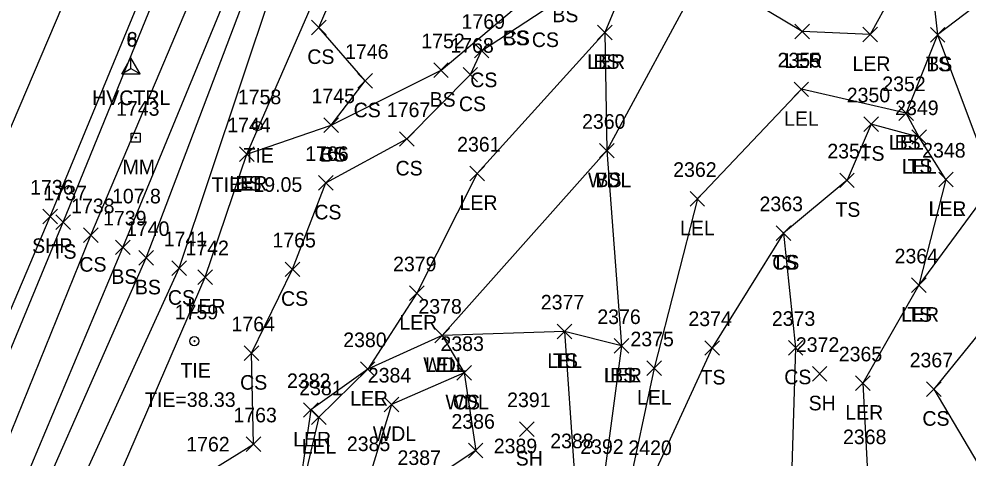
# Model space of a CAD drawing. Extents: x 1483143 to 1488182, y 802902 to 807581.
# Drawn here: x 1487782.5 to 1487912.6, y 806252.6 to 806312.7 of the extents above; entities that cross this region are included whole.
import ezdxf

# ---------------------------------------------------------------- set-up
doc = ezdxf.new("R2010")
doc.units = 0
for name, color, linetype in [('C_A', 7, 'Continuous'), ('C_C', 7, 'Continuous'), ('C_I', 7, 'Continuous'), ('CBP', 7, 'Continuous'), ('CPSM', 7, 'Continuous'), ('L_A', 7, 'Continuous'), ('L_I', 7, 'Continuous'), ('L_TIC', 7, 'Continuous'), ('LARO', 7, 'Continuous'), ('LAWA', 7, 'Continuous'), ('LELB', 7, 'Continuous'), ('P_A', 7, 'Continuous'), ('P_I', 7, 'Continuous'), ('P_TIC', 7, 'Continuous'), ('PET', 7, 'Continuous'), ('PSP', 7, 'Continuous'), ('S_A', 7, 'Continuous'), ('S_C', 7, 'Continuous'), ('S_I', 7, 'Continuous'), ('SRM', 7, 'Continuous')]:
    doc.layers.add(name, color=color, linetype=linetype)

msp = doc.modelspace()

# ---------------------------------------------------------------- linework, layer by layer
at = {"layer": 'CBP'}
for centre, radius in [((1487815.21, 806298.01), 0.625), ((1487815.21, 806298.01), 0.0833), ((1487806.57, 806268.56), 0.625), ((1487806.57, 806268.56), 0.0833)]:
    msp.add_circle(centre, radius, dxfattribs=at)
at = {"layer": 'CPSM'}
for p, q in [((1487796.61, 806305.17), (1487797.86, 806307.34)), ((1487796.62, 806305.17), (1487797.87, 806307.34)), ((1487799.11, 806305.17), (1487797.86, 806307.34)), ((1487797.86, 806305.89), (1487797.86, 806307.34)), ((1487799.12, 806305.17), (1487797.87, 806307.34)), ((1487797.87, 806305.9), (1487797.87, 806307.34)), ((1487796.61, 806305.17), (1487797.86, 806305.89)), ((1487796.61, 806305.17), (1487799.11, 806305.17)), ((1487796.62, 806305.17), (1487797.87, 806305.9)), ((1487796.62, 806305.17), (1487799.12, 806305.17)), ((1487797.86, 806305.89), (1487797.86, 806305.89)), ((1487797.86, 806305.89), (1487799.11, 806305.17)), ((1487797.87, 806305.9), (1487797.87, 806305.9)), ((1487797.87, 806305.9), (1487799.12, 806305.17))]:
    msp.add_line(p, q, dxfattribs=at)
at = {"layer": 'L_TIC'}
for points in [[(1487822.6, 806310.52), (1487824.6, 806312.52)], [(1487824.6, 806310.52), (1487822.6, 806312.52)], [(1487861.81, 806309.84), (1487863.81, 806311.84)], [(1487863.81, 806309.84), (1487861.81, 806311.84)], [(1487861.81, 806309.84), (1487863.81, 806311.84)], [(1487863.81, 806309.84), (1487861.81, 806311.84)], [(1487888.85, 806309.98), (1487890.85, 806311.98)], [(1487890.85, 806309.98), (1487888.85, 806311.98)], [(1487898.17, 806309.55), (1487900.17, 806311.55)], [(1487900.17, 806309.55), (1487898.17, 806311.55)], [(1487907.42, 806309.52), (1487909.42, 806311.52)], [(1487909.42, 806309.52), (1487907.42, 806311.52)], [(1487907.42, 806309.52), (1487909.42, 806311.52)], [(1487909.42, 806309.52), (1487907.42, 806311.52)], [(1487844.93, 806307.34), (1487846.93, 806309.34)], [(1487846.93, 806307.34), (1487844.93, 806309.34)], [(1487839.36, 806304.67), (1487841.36, 806306.67)], [(1487841.36, 806304.67), (1487839.36, 806306.67)], [(1487828.95, 806303.22), (1487830.95, 806305.22)], [(1487830.95, 806303.22), (1487828.95, 806305.22)], [(1487843.38, 806304.06), (1487845.38, 806306.06)], [(1487845.38, 806304.06), (1487843.38, 806306.06)], [(1487888.74, 806302.05), (1487890.74, 806304.05)], [(1487890.74, 806302.05), (1487888.74, 806304.05)], [(1487903.09, 806298.8), (1487905.09, 806300.8)], [(1487905.09, 806298.8), (1487903.09, 806300.8)], [(1487903.09, 806298.8), (1487905.09, 806300.8)], [(1487905.09, 806298.8), (1487903.09, 806300.8)], [(1487824.31, 806297.15), (1487826.31, 806299.15)], [(1487826.31, 806297.15), (1487824.31, 806299.15)], [(1487824.31, 806297.15), (1487826.31, 806299.15)], [(1487826.31, 806297.15), (1487824.31, 806299.15)], [(1487898.31, 806297.27), (1487900.31, 806299.27)], [(1487900.31, 806297.27), (1487898.31, 806299.27)], [(1487834.69, 806295.25), (1487836.69, 806297.25)], [(1487836.69, 806295.25), (1487834.69, 806297.25)], [(1487904.87, 806295.52), (1487906.87, 806297.52)], [(1487906.87, 806295.52), (1487904.87, 806297.52)], [(1487904.87, 806295.52), (1487906.87, 806297.52)], [(1487906.87, 806295.52), (1487904.87, 806297.52)], [(1487812.76, 806293.17), (1487814.76, 806295.17)], [(1487814.76, 806293.17), (1487812.76, 806295.17)], [(1487812.76, 806293.17), (1487814.76, 806295.17)], [(1487814.76, 806293.17), (1487812.76, 806295.17)], [(1487862.09, 806293.65), (1487864.09, 806295.65)], [(1487864.09, 806293.65), (1487862.09, 806295.65)], [(1487862.09, 806293.65), (1487864.09, 806295.65)], [(1487864.09, 806293.65), (1487862.09, 806295.65)], [(1487844.31, 806290.53), (1487846.31, 806292.53)], [(1487846.31, 806290.53), (1487844.31, 806292.53)], [(1487823.56, 806289.24), (1487825.56, 806291.24)], [(1487825.56, 806289.24), (1487823.56, 806291.24)], [(1487895, 806289.59), (1487897, 806291.59)], [(1487897, 806289.59), (1487895, 806291.59)], [(1487908.56, 806289.7), (1487910.56, 806291.7)], [(1487910.56, 806289.7), (1487908.56, 806291.7)], [(1487908.56, 806289.7), (1487910.56, 806291.7)], [(1487910.56, 806289.7), (1487908.56, 806291.7)], [(1487874.49, 806287.06), (1487876.49, 806289.06)], [(1487876.49, 806287.06), (1487874.49, 806289.06)], [(1487787.58, 806283.85), (1487789.58, 806285.85)], [(1487789.58, 806283.85), (1487787.58, 806285.85)], [(1487886.31, 806282.36), (1487888.31, 806284.36)], [(1487888.31, 806282.36), (1487886.31, 806284.36)], [(1487886.31, 806282.36), (1487888.31, 806284.36)], [(1487888.31, 806282.36), (1487886.31, 806284.36)], [(1487791.36, 806282.08), (1487793.36, 806284.08)], [(1487793.36, 806282.08), (1487791.36, 806284.08)], [(1487795.75, 806280.41), (1487797.75, 806282.41)], [(1487797.75, 806280.41), (1487795.75, 806282.41)], [(1487798.97, 806278.97), (1487800.97, 806280.97)], [(1487800.97, 806278.97), (1487798.97, 806280.97)], [(1487803.48, 806277.55), (1487805.48, 806279.55)], [(1487805.48, 806277.55), (1487803.48, 806279.55)], [(1487819, 806277.4), (1487821, 806279.4)], [(1487821, 806277.4), (1487819, 806279.4)], [(1487807.03, 806276.33), (1487809.03, 806278.33)], [(1487809.03, 806276.33), (1487807.03, 806278.33)], [(1487904.83, 806275.22), (1487906.83, 806277.22)], [(1487906.83, 806275.22), (1487904.83, 806277.22)], [(1487904.83, 806275.22), (1487906.83, 806277.22)], [(1487906.83, 806275.22), (1487904.83, 806277.22)], [(1487836.06, 806274.13), (1487838.06, 806276.13)], [(1487838.06, 806274.13), (1487836.06, 806276.13)], [(1487839.52, 806268.33), (1487841.52, 806270.33)], [(1487841.52, 806268.33), (1487839.52, 806270.33)], [(1487839.52, 806268.33), (1487841.52, 806270.33)], [(1487841.52, 806268.33), (1487839.52, 806270.33)], [(1487856.3, 806268.9), (1487858.3, 806270.9)], [(1487858.3, 806268.9), (1487856.3, 806270.9)], [(1487856.3, 806268.9), (1487858.3, 806270.9)], [(1487858.3, 806268.9), (1487856.3, 806270.9)], [(1487864.1, 806266.91), (1487866.1, 806268.91)], [(1487866.1, 806266.91), (1487864.1, 806268.91)], [(1487864.1, 806266.91), (1487866.1, 806268.91)], [(1487866.1, 806266.91), (1487864.1, 806268.91)], [(1487864.1, 806266.91), (1487866.1, 806268.91)], [(1487866.1, 806266.91), (1487864.1, 806268.91)], [(1487876.52, 806266.63), (1487878.52, 806268.63)], [(1487878.52, 806266.63), (1487876.52, 806268.63)], [(1487887.96, 806266.66), (1487889.96, 806268.66)], [(1487889.96, 806266.66), (1487887.96, 806268.66)], [(1487813.39, 806265.92), (1487815.39, 806267.92)], [(1487815.39, 806265.92), (1487813.39, 806267.92)], [(1487829.31, 806263.75), (1487831.31, 806265.75)], [(1487831.31, 806263.75), (1487829.31, 806265.75)], [(1487829.31, 806263.75), (1487831.31, 806265.75)], [(1487831.31, 806263.75), (1487829.31, 806265.75)], [(1487842.55, 806263.22), (1487844.55, 806265.22)], [(1487844.55, 806263.22), (1487842.55, 806265.22)], [(1487842.55, 806263.22), (1487844.55, 806265.22)], [(1487844.55, 806263.22), (1487842.55, 806265.22)], [(1487868.58, 806263.86), (1487870.58, 806265.86)], [(1487870.58, 806263.86), (1487868.58, 806265.86)], [(1487891.25, 806263.09), (1487893.25, 806265.09)], [(1487893.25, 806263.09), (1487891.25, 806265.09)], [(1487897.18, 806261.8), (1487899.18, 806263.8)], [(1487899.18, 806261.8), (1487897.18, 806263.8)], [(1487906.89, 806260.98), (1487908.89, 806262.98)], [(1487908.89, 806260.98), (1487906.89, 806262.98)], [(1487832.59, 806258.9), (1487834.59, 806260.9)], [(1487834.59, 806258.9), (1487832.59, 806260.9)], [(1487821.51, 806258.14), (1487823.51, 806260.14)], [(1487823.51, 806258.14), (1487821.51, 806260.14)], [(1487822.62, 806257.16), (1487824.62, 806259.16)], [(1487824.62, 806257.16), (1487822.62, 806259.16)], [(1487851.11, 806255.53), (1487853.11, 806257.53)], [(1487853.11, 806255.53), (1487851.11, 806257.53)], [(1487813.65, 806253.45), (1487815.65, 806255.45)], [(1487815.65, 806253.45), (1487813.65, 806255.45)], [(1487844.11, 806252.58), (1487846.11, 806254.58)], [(1487846.11, 806252.58), (1487844.11, 806254.58)]]:
    msp.add_lwpolyline(points, dxfattribs=at)
at = {"layer": 'LARO'}
for points in [[(1487666.95, 805964.97), (1487680.31, 805984.75), (1487702.99, 806037.2), (1487715.7, 806058.03), (1487734.3, 806108.53), (1487742.02, 806134.63), (1487761.66, 806177.53), (1487786.65, 806227.9), (1487808.03, 806277.33), (1487813.76, 806294.17), (1487828.9, 806329), (1487831.91, 806346.68), (1487843.29, 806372.21), (1487845.69, 806380.48), (1487852.63, 806386.9), (1487863.18, 806416.3)], [(1487938.33, 806405.75), (1487927.08, 806402.62), (1487919.67, 806403.09), (1487914.11, 806409.79), (1487906.78, 806399.47), (1487893.33, 806381.44), (1487887.6, 806370.68), (1487880.83, 806355.03), (1487873.24, 806335.95), (1487862.81, 806310.84), (1487845.31, 806291.53), (1487837.06, 806275.13), (1487830.31, 806264.75), (1487822.51, 806259.14), (1487820.37, 806244.37)], [(1487906.74, 806373.16), (1487907.59, 806351.7), (1487906.84, 806324.5), (1487899.17, 806310.55), (1487889.85, 806310.98), (1487876.29, 806319.09)], [(1487909.56, 806290.7), (1487905.87, 806296.52), (1487904.09, 806299.8), (1487889.74, 806303.05), (1487875.49, 806288.06), (1487869.58, 806264.86), (1487865.87, 806247.52), (1487863.99, 806239.72), (1487861.46, 806231.13), (1487859.56, 806216.52), (1487857.78, 806202.84), (1487854.62, 806182.96), (1487851.71, 806170.77)], [(1487909.56, 806290.7), (1487905.83, 806276.22), (1487898.18, 806262.8), (1487898.76, 806251.46), (1487896.26, 806247.35), (1487888.51, 806232.47), (1487866.93, 806215.67), (1487865.79, 806201.15), (1487860.88, 806184.43), (1487851.71, 806170.77)], [(1487865.1, 806267.91), (1487857.3, 806269.9), (1487840.52, 806269.33), (1487830.31, 806264.75), (1487823.62, 806258.16), (1487820.37, 806244.37)], [(1487865.1, 806267.91), (1487862.7, 806250.12), (1487854.75, 806240.93), (1487852, 806231.22), (1487849.04, 806223.36), (1487844.9, 806204.43)]]:
    msp.add_lwpolyline(points, dxfattribs=at)
at = {"layer": 'LAWA'}
msp.add_lwpolyline([(1487942.37, 806424.18), (1487942.13, 806400.96), (1487924.66, 806393.36), (1487906.74, 806373.16), (1487899.59, 806370.18), (1487890.83, 806350.54), (1487893.79, 806329.46), (1487876.29, 806319.09), (1487863.09, 806294.65), (1487840.52, 806269.33), (1487843.55, 806264.22), (1487833.59, 806259.9), (1487830.72, 806250.51), (1487828.92, 806235.37), (1487823.44, 806218.85), (1487816.5, 806198.3), (1487812.31, 806191.59), (1487811.73, 806182.07)], dxfattribs=at)
at = {"layer": 'LELB'}
for points in [[(1487959.91, 806445.22), (1487960.75, 806398.74), (1487951.5, 806373.39), (1487932.63, 806356.69), (1487906.84, 806324.5), (1487908.42, 806310.52), (1487916.06, 806290.13), (1487905.83, 806276.22)], [(1487406.66, 805485.41), (1487431.45, 805531.24), (1487454.84, 805575.74), (1487473.75, 805612.05), (1487489.43, 805642.37), (1487507.64, 805678.53), (1487524.82, 805711.39), (1487541.86, 805746.09), (1487557.67, 805776.44), (1487575.49, 805812.01), (1487597.52, 805857.93), (1487620.62, 805906.82), (1487641.85, 805951.94), (1487662.18, 805996.35), (1487684.09, 806043.93), (1487694.42, 806066.95), (1487726.58, 806140.7), (1487745.85, 806185.55), (1487769.04, 806237.65), (1487788.58, 806284.85), (1487808.3, 806333.26), (1487827.52, 806379.6), (1487850.09, 806437.73)], [(1487410.04, 805483.24), (1487436.07, 805529.53), (1487459.78, 805575.03), (1487477.42, 805609.67), (1487492.45, 805639.09), (1487509.86, 805677.27), (1487528.68, 805708.85), (1487545.3, 805744.17), (1487561.79, 805774.32), (1487579.7, 805810.21), (1487602.04, 805856.31), (1487624.97, 805905.57), (1487645.72, 805950.02), (1487667.21, 805993.1), (1487687.16, 806043.23), (1487699.2, 806065.16), (1487730.65, 806138.87), (1487749.96, 806183.58), (1487772.93, 806235.17), (1487792.36, 806283.08), (1487812.9, 806331.5), (1487831.61, 806378.23), (1487855.61, 806436.65)], [(1487413.83, 805481.53), (1487440.22, 805526.89), (1487464.36, 805572.85), (1487481.71, 805606.55), (1487496.63, 805636.25), (1487514.9, 805673.97), (1487535.8, 805705.94), (1487549.07, 805741.59), (1487566.17, 805772.22), (1487583.99, 805807.69), (1487605.26, 805855.28), (1487629.33, 805903.01), (1487650.26, 805948.76), (1487670.48, 805991.25), (1487690.28, 806041.74), (1487702.22, 806061.37), (1487704.47, 806066.39), (1487735.28, 806136.71), (1487754, 806182.42), (1487776.55, 806233.47), (1487796.75, 806281.41), (1487816.88, 806330.25), (1487835.19, 806376.59), (1487859.78, 806434.97)], [(1487417, 805480.8), (1487442.28, 805525.8), (1487466.47, 805571.82), (1487483.84, 805604.86), (1487498.25, 805635.76), (1487518.24, 805671.86), (1487538.47, 805704.77), (1487552.2, 805739.67), (1487568.17, 805771.84), (1487585.97, 805806.76), (1487609.39, 805853.47), (1487632.34, 805900.81), (1487653.02, 805947.32), (1487672.59, 805990.01), (1487694.92, 806039.27), (1487707.45, 806059.25), (1487710.05, 806064.3), (1487737.97, 806135.43), (1487757.4, 806181.42), (1487778.76, 806231.94), (1487799.97, 806279.97), (1487818.92, 806329.91), (1487837.5, 806376), (1487863.45, 806433.38)], [(1487539.8, 805706.7), (1487554.99, 805738.51), (1487564.78, 805761.24), (1487572.42, 805770.06), (1487590.42, 805804.18), (1487613.31, 805851.36), (1487639.64, 805896.3), (1487657.07, 805945.9), (1487666.95, 805964.97), (1487675.89, 805987.99), (1487698.82, 806037.9), (1487713.56, 806059.8), (1487740.03, 806134.78), (1487759.8, 806179.98), (1487782.43, 806230.23), (1487804.48, 806278.55), (1487821.45, 806329.34), (1487839.66, 806374.66), (1487865.87, 806433.14)], [(1487966.07, 806415.18), (1487969.53, 806392.86), (1487952.94, 806357.28), (1487940.19, 806330.57), (1487921.69, 806320.66), (1487908.42, 806310.52), (1487904.09, 806299.8)], [(1487808.19, 806250.46), (1487814.65, 806254.45), (1487814.39, 806266.92), (1487820, 806278.4), (1487824.56, 806290.24), (1487835.69, 806296.25), (1487844.38, 806305.06), (1487845.93, 806308.34), (1487854.37, 806313.84), (1487858.64, 806318.45), (1487862.61, 806322.32), (1487863.81, 806332.53), (1487867.72, 806348.95), (1487870.05, 806365.59), (1487870.12, 806383.98), (1487868.69, 806390.08), (1487866.81, 806394.33), (1487869.32, 806406.71)], [(1487813.76, 806294.17), (1487825.31, 806298.15), (1487840.36, 806305.67), (1487850.38, 806314.09), (1487857.18, 806317.24), (1487858.03, 806321.04), (1487853.69, 806320.47), (1487848.49, 806331.05), (1487865.24, 806340.88), (1487856.77, 806352.5), (1487853.63, 806373.17)], [(1487940.19, 806330.57), (1487936.41, 806308.22), (1487924.68, 806281.58), (1487917.48, 806273.83), (1487907.89, 806261.98), (1487917.31, 806246.1), (1487904.77, 806206.09), (1487890.85, 806175.33)], [(1487825.31, 806298.15), (1487829.95, 806304.22), (1487823.6, 806311.52), (1487827.41, 806320.39), (1487830.6, 806326.63), (1487839.5, 806329.06), (1487846.74, 806322.05), (1487850.38, 806314.09)], [(1487862.81, 806310.84), (1487863.09, 806294.65), (1487865.1, 806267.91)], [(1487905.87, 806296.52), (1487899.31, 806298.27), (1487896, 806290.59), (1487887.31, 806283.36), (1487877.52, 806267.63), (1487869.38, 806249.97), (1487869.35, 806240.62), (1487866.86, 806230.63), (1487866.93, 806215.67), (1487870.72, 806201.06), (1487871.88, 806182.87), (1487866.74, 806152.06), (1487880.05, 806151.29), (1487878.4, 806134.82), (1487882.05, 806128.03)], [(1487887.31, 806283.36), (1487888.96, 806267.66), (1487888.27, 806245.35), (1487888.51, 806232.47), (1487885.08, 806216.45), (1487883.32, 806178.65), (1487880.05, 806151.29), (1487872.71, 806136.11), (1487871.18, 806117.39)], [(1487857.3, 806269.9), (1487858.59, 806250.9), (1487850.85, 806250.21), (1487845.45, 806239.59)], [(1487843.55, 806264.22), (1487845.11, 806253.58), (1487837.65, 806248.61), (1487845.45, 806239.59)]]:
    msp.add_lwpolyline(points, dxfattribs=at)
at = {"layer": 'P_TIC'}
for points in [[(1487785.8, 806284.64), (1487787.8, 806286.64)], [(1487787.8, 806284.64), (1487785.8, 806286.64)]]:
    msp.add_lwpolyline(points, dxfattribs=at)
at = {"layer": 'PET'}
msp.add_lwpolyline([(1487396.33, 805490.41), (1487421.9, 805537.94), (1487444.13, 805580.16), (1487464.29, 805618.83), (1487479.8, 805648.39), (1487498.08, 805684.27), (1487514.57, 805717.15), (1487530.55, 805749.06), (1487547.16, 805782.47), (1487564.33, 805817.54), (1487585.71, 805863.32), (1487608.89, 805911.38), (1487630.35, 805956.68), (1487651.22, 806001.25), (1487672.63, 806048.33), (1487683.65, 806072.29), (1487715.61, 806144.47), (1487735.35, 806190.47), (1487757.48, 806241.03), (1487777.65, 806289.15), (1487798.25, 806337.46), (1487817.05, 806384.04), (1487839.67, 806441.4)], dxfattribs=at)
at = {"layer": 'PSP'}
msp.add_lwpolyline([(1487405.03, 805486.21), (1487429.8, 805532.42), (1487452.92, 805576.31), (1487472.37, 805613.24), (1487487.86, 805643.29), (1487506.35, 805679.4), (1487523.34, 805712.45), (1487540.38, 805746.64), (1487556.03, 805777.85), (1487573.44, 805813.27), (1487595.34, 805859.04), (1487618.37, 805906.67), (1487640.09, 805952.42), (1487660.18, 805997.21), (1487682.38, 806044.71), (1487693.04, 806068.56), (1487725.12, 806141.19), (1487744.39, 806185.87), (1487766.81, 806238.55), (1487786.8, 806285.64), (1487806.77, 806333.93), (1487825.55, 806380.21), (1487847.81, 806437.56)], dxfattribs=at)
at = {"layer": 'SRM'}
msp.add_lwpolyline([(1487797.9, 806297.05), (1487799.15, 806297.05), (1487799.15, 806295.8), (1487797.9, 806295.8)], close=True, dxfattribs=at)
msp.add_circle((1487798.53, 806296.43), 0.0833, dxfattribs=at)

# ---------------------------------------------------------------- texts
at = {"layer": 'C_A'}
for s, p in [('HVCTRL', (1487792.55, 806300.89)), ('HVCTRL', (1487792.56, 806300.9)), ('TIE', (1487813.29, 806293.01)), ('TIE', (1487804.65, 806263.56))]:
    msp.add_text(s, height=2, dxfattribs=at).set_placement(p)
at = {"layer": 'C_C'}
for s, p in [('TIE=19.05', (1487808.93, 806289.01)), ('TIE=38.33', (1487799.8, 806259.56))]:
    msp.add_text(s, height=2, dxfattribs=at).set_placement(p)
at = {"layer": 'C_I'}
for s, p in [('6', (1487797.25, 806308.9)), ('8', (1487797.3, 806308.89)), ('1758', (1487812.52, 806301.01)), ('1759', (1487803.87, 806271.56))]:
    msp.add_text(s, height=2, dxfattribs=at).set_placement(p)
at = {"layer": 'L_A'}
for s, p in [('BS', (1487855.62, 806312.24)), ('CS', (1487848.82, 806309.09)), ('BS', (1487848.82, 806309.09)), ('CS', (1487852.81, 806308.84)), ('CS', (1487822.04, 806306.52)), ('LER', (1487860.39, 806305.84)), ('BS', (1487861.25, 806305.84)), ('LER', (1487887.43, 806305.98)), ('LER', (1487896.75, 806305.55)), ('TS', (1487906.83, 806305.52)), ('BS', (1487906.86, 806305.52)), ('CS', (1487844.37, 806303.34)), ('BS', (1487838.8, 806300.67)), ('CS', (1487828.39, 806299.22)), ('CS', (1487842.82, 806300.06)), ('LEL', (1487887.37, 806298.05)), ('LEL', (1487901.73, 806294.8)), ('BS', (1487902.53, 806294.8)), ('CS', (1487823.75, 806293.15)), ('BS', (1487823.75, 806293.15)), ('TS', (1487897.72, 806293.27)), ('LEL', (1487903.51, 806291.52)), ('TS', (1487904.28, 806291.52)), ('CS', (1487834.13, 806291.25)), ('LER', (1487811.35, 806289.17)), ('BS', (1487812.2, 806289.17)), ('WDL', (1487860.5, 806289.65)), ('BS', (1487861.53, 806289.65)), ('LER', (1487842.9, 806286.53)), ('CS', (1487823, 806285.24)), ('TS', (1487894.41, 806285.59)), ('LER', (1487907.15, 806285.7)), ('LEL', (1487907.2, 806285.7)), ('LEL', (1487873.12, 806283.06)), ('TS', (1487786.99, 806279.85)), ('TS', (1487885.72, 806278.36)), ('CS', (1487885.75, 806278.36)), ('CS', (1487790.8, 806278.08)), ('BS', (1487795.19, 806276.41)), ('BS', (1487798.41, 806274.97)), ('CS', (1487802.93, 806273.55)), ('CS', (1487818.44, 806273.4)), ('LER', (1487805.62, 806272.33)), ('LER', (1487903.41, 806271.22)), ('TS', (1487904.24, 806271.22)), ('LER', (1487834.65, 806270.13)), ('WDL', (1487837.94, 806264.33)), ('LEL', (1487838.16, 806264.33)), ('LEL', (1487854.94, 806264.9)), ('TS', (1487855.71, 806264.9)), ('LER', (1487862.68, 806262.91)), ('LEL', (1487862.74, 806262.91)), ('BS', (1487863.54, 806262.91)), ('CS', (1487812.83, 806261.92)), ('TS', (1487875.93, 806262.63)), ('CS', (1487887.4, 806262.66)), ('LER', (1487827.89, 806259.75)), ('LEL', (1487827.94, 806259.75)), ('WDL', (1487840.97, 806259.22)), ('CS', (1487841.99, 806259.22)), ('LEL', (1487867.22, 806259.86)), ('SH', (1487890.74, 806259.09)), ('LER', (1487895.76, 806257.8)), ('CS', (1487906.33, 806256.98)), ('LER', (1487820.09, 806254.14)), ('WDL', (1487831.01, 806254.9)), ('LEL', (1487821.26, 806253.16)), ('SH', (1487850.6, 806251.53))]:
    msp.add_text(s, height=2, dxfattribs=at).set_placement(p)
at = {"layer": 'L_I'}
for s, p in [('1769', (1487843.18, 806311.34)), ('1752', (1487837.66, 806308.67)), ('1746', (1487827.21, 806307.22)), ('1768', (1487841.64, 806308.06)), ('2355', (1487886.48, 806306.05)), ('2352', (1487900.83, 806302.8)), ('2352', (1487900.83, 806302.8)), ('1745', (1487822.62, 806301.15)), ('1745', (1487822.62, 806301.15)), ('2350', (1487895.96, 806301.27)), ('1767', (1487832.94, 806299.25)), ('2349', (1487902.6, 806299.52)), ('2349', (1487902.6, 806299.52)), ('1744', (1487811.07, 806297.17)), ('1744', (1487811.07, 806297.17)), ('2360', (1487859.69, 806297.65)), ('2360', (1487859.69, 806297.65)), ('2361', (1487842.57, 806294.53)), ('1766', (1487821.76, 806293.24)), ('2351', (1487893.3, 806293.59)), ('2348', (1487906.3, 806293.7)), ('2348', (1487906.3, 806293.7)), ('2362', (1487872.18, 806291.06)), ('1737', (1487785.89, 806287.85)), ('2363', (1487884.01, 806286.36)), ('2363', (1487884.01, 806286.36)), ('1738', (1487789.67, 806286.08)), ('1739', (1487794.05, 806284.41)), ('1740', (1487797.19, 806282.97)), ('1741', (1487802.36, 806281.55)), ('1765', (1487817.26, 806281.4)), ('1742', (1487805.34, 806280.33)), ('2364', (1487902.52, 806279.22)), ('2364', (1487902.52, 806279.22)), ('2379', (1487833.79, 806278.13)), ('2378', (1487837.26, 806272.33)), ('2378', (1487837.26, 806272.33)), ('2377', (1487854.04, 806272.9)), ('2377', (1487854.04, 806272.9)), ('2376', (1487861.78, 806270.91)), ('2376', (1487861.78, 806270.91)), ('2376', (1487861.78, 806270.91)), ('2374', (1487874.26, 806270.63)), ('2373', (1487885.7, 806270.66)), ('1764', (1487811.65, 806269.92)), ('2380', (1487826.96, 806267.75)), ('2380', (1487826.96, 806267.75)), ('2383', (1487840.29, 806267.22)), ('2383', (1487840.29, 806267.22)), ('2375', (1487866.32, 806267.86)), ('2372', (1487888.99, 806267.09)), ('2365', (1487894.87, 806265.8)), ('2367', (1487904.58, 806264.98)), ('2384', (1487830.33, 806262.9)), ('2382', (1487819.25, 806262.14)), ('2381', (1487820.93, 806261.16)), ('2391', (1487849.42, 806259.53)), ('1763', (1487811.91, 806257.45)), ('2386', (1487841.79, 806256.58)), ('2388', (1487855.33, 806253.9)), ('2368', (1487895.45, 806254.46)), ('2368', (1487895.45, 806254.46)), ('1762', (1487805.45, 806253.46)), ('2385', (1487827.46, 806253.51)), ('2389', (1487847.59, 806253.21)), ('2392', (1487859.44, 806253.12)), ('2392', (1487859.44, 806253.12)), ('2420', (1487866.04, 806252.97)), ('2387', (1487834.4, 806251.61))]:
    msp.add_text(s, height=2, dxfattribs=at).set_placement(p)
at = {"layer": 'P_A'}
msp.add_text('SHP', height=2, dxfattribs=at).set_placement((1487784.33, 806280.64))
at = {"layer": 'P_I'}
msp.add_text('1736', height=2, dxfattribs=at).set_placement((1487784.05, 806288.64))
at = {"layer": 'S_A'}
msp.add_text('MM', height=2, dxfattribs=at).set_placement((1487796.72, 806291.43))
at = {"layer": 'S_C'}
msp.add_text('107.8', height=2, dxfattribs=at).set_placement((1487795.27, 806287.43))
at = {"layer": 'S_I'}
msp.add_text('1743', height=2, dxfattribs=at).set_placement((1487795.83, 806299.43))

doc.saveas('drawing.dxf')
